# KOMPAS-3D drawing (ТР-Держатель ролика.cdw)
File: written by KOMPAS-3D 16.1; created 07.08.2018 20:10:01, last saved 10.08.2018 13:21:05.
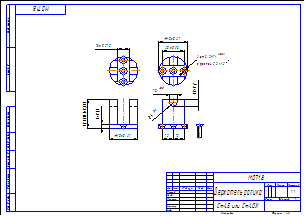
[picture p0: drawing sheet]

Sheet 1: A3, landscape

Title block, sheet 1: name: Держатель ролика; designation: М0718; material: Ст45 или Ст40Х; scale: 1:1; sheets: 1; sheet format: A3; stored path: C:\Users\User\Desktop\Станки\Малый 0718\ТР-Крепление ролика вертикального.cdw

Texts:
  User
  с фаской 2,5 45
  JS14( 0,31)
  Стандартные изделия
  Винт А.М5-6gx18 ГОСТ 17475-80
  Винт
  ГОСТ 17475-80
  А.М5-6gx18
  Обозначение стандарта
  Типоразмер
Dimensions and other numbers on the sheet: 16±0,215; 10±0,2; 5±0,15; 15; 30±0,26; 40±0,31; 3 отв.; 1:1; 1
